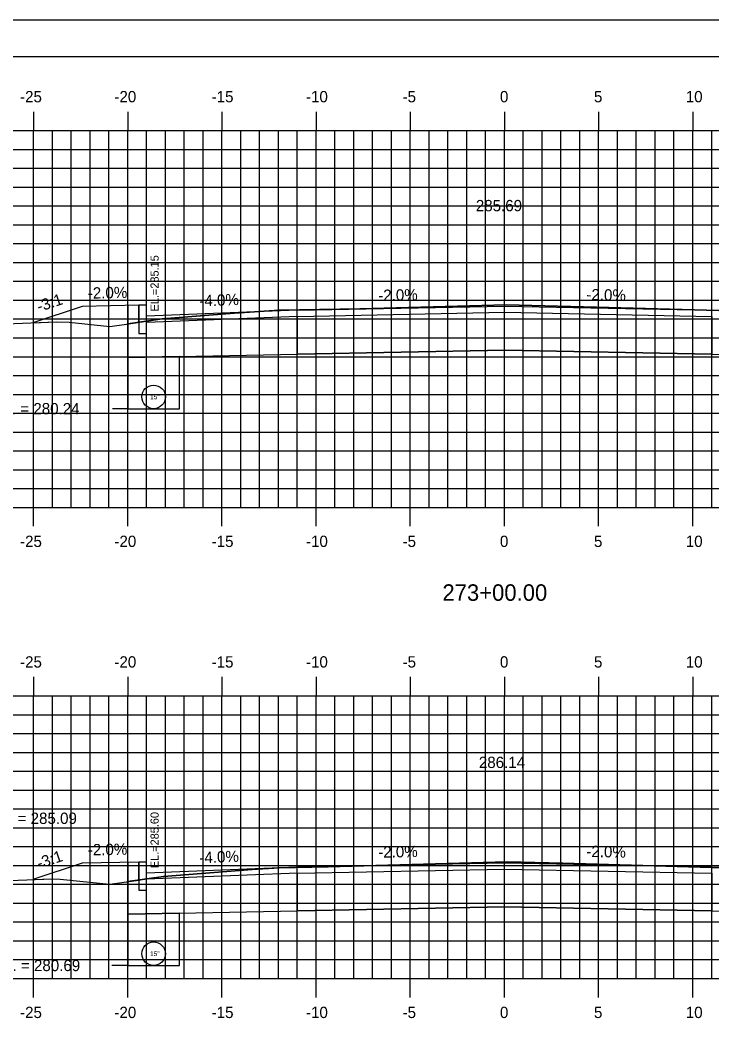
# Model space of a CAD drawing. Extents: x 852672 to 852842, y 366268 to 366378.
# Drawn here: x 852729.4 to 852766.1, y 366324.2 to 366378.2 of the extents above; entities that cross this region are included whole.
import ezdxf

# ---------------------------------------------------------------- set-up
doc = ezdxf.new("R2010")
doc.units = 0
for name, color, linetype in [('ANNOTATION', 7, 'Continuous'), ('BORDER', 7, 'Continuous'), ('D_Curb_Type_1_Lt', 7, 'Continuous'), ('D_Roadway_Centerline_Text', 7, 'Continuous'), ('D_Roadway_Edge_Shoulder', 7, 'Continuous'), ('D_Roadway_FinishedGrade', 7, 'Continuous'), ('D_Roadway_SubGrade', 7, 'Continuous'), ('D_Text_Standard', 7, 'Continuous'), ('H_V ANNOTATION', 7, 'Continuous'), ('JUNK COM EXC', 7, 'Continuous'), ('JUNK FILL', 7, 'Continuous'), ('junk strct exc', 7, 'Continuous'), ('MAJOR', 7, 'Continuous'), ('MINOR', 7, 'Continuous'), ('PDRAIN', 7, 'Continuous'), ('PLOT BOUNDARY', 7, 'Continuous'), ('S_Roadway_Centerline', 7, 'Continuous')]:
    doc.layers.add(name, color=color, linetype=linetype)

msp = doc.modelspace()

# ---------------------------------------------------------------- linework, layer by layer
at = {"layer": 'BORDER'}
msp.add_line((852840.097, 366376.236), (852680.097, 366376.236), dxfattribs=at)
at = {"layer": 'D_Curb_Type_1_Lt'}
for points in [[(852735.68, 366363.057), (852735.68, 366361.557), (852736.096, 366361.557), (852736.096, 366363.057)], [(852735.68, 366333.508), (852735.68, 366332.008), (852736.096, 366332.008), (852736.096, 366333.508)]]:
    msp.add_lwpolyline(points, close=True, dxfattribs=at)
at = {"layer": 'D_Roadway_Edge_Shoulder'}
msp.add_line((852744.096, 366362.793), (852736.096, 366362.473), dxfattribs=at)
for points in [[(852744.096, 366362.793), (852755.096, 366363.013), (852766.096, 366362.793)], [(852736.096, 366332.925), (852744.096, 366333.245), (852755.096, 366333.464), (852766.096, 366333.245), (852774.096, 366332.924)]]:
    msp.add_lwpolyline(points, dxfattribs=at)
at = {"layer": 'D_Roadway_FinishedGrade'}
for points in [[(852732.68, 366362.997), (852730.062, 366362.124)], [(852735.68, 366363.057), (852732.68, 366362.997)], [(852732.68, 366333.448), (852730.063, 366332.576)], [(852735.68, 366333.508), (852732.68, 366333.448)]]:
    msp.add_lwpolyline(points, dxfattribs=at)
at = {"layer": 'D_Roadway_SubGrade'}
for points in [[(852735.096, 366363.045), (852735.096, 366360.28)], [(852735.096, 366360.28), (852744.11, 366360.461), (852744.11, 366362.461), (852736.11, 366362.141)], [(852735.096, 366333.496), (852735.096, 366330.732)], [(852735.096, 366330.732), (852744.106, 366330.912), (852744.106, 366332.912), (852736.096, 366332.591)]]:
    msp.add_lwpolyline(points, dxfattribs=at)
for points in [[(852744.11, 366360.461), (852744.11, 366362.461), (852755.11, 366362.681), (852766.11, 366362.461), (852766.11, 366360.461), (852755.11, 366360.681)], [(852744.106, 366330.912), (852744.106, 366332.912), (852755.106, 366333.132), (852766.106, 366332.912), (852766.106, 366330.912), (852755.106, 366331.132)]]:
    msp.add_lwpolyline(points, close=True, dxfattribs=at)
at = {"layer": 'D_Text_Standard'}
for points in [[(852735.096, 366357.567), (852734.968, 366357.567), (852734.288, 366357.567)], [(852735.096, 366328.017), (852734.936, 366328.017), (852734.256, 366328.017)]]:
    msp.add_lwpolyline(points, dxfattribs=at)
at = {"layer": 'JUNK COM EXC'}
for points in [[(852735.096, 366362.066), (852735.096, 366360.28), (852744.11, 366360.461), (852755.11, 366360.681), (852766.11, 366360.461), (852775.086, 366360.282), (852775.096, 366362.456), (852768.422, 366362.719), (852759.991, 366362.96), (852755.187, 366363.083), (852747.417, 366362.872), (852743.133, 366362.791), (852740.774, 366362.627), (852736.929, 366362.331)], [(852735.096, 366332.469), (852735.096, 366330.732), (852744.106, 366330.912), (852755.106, 366331.132), (852766.106, 366330.912), (852775.096, 366330.732), (852775.096, 366332.352), (852779.101, 366332.433), (852779.101, 366332.787), (852775.096, 366332.902), (852773.379, 366332.951), (852768.512, 366333.143), (852758.198, 366333.438), (852755.238, 366333.514), (852745.742, 366333.256), (852743.139, 366333.207), (852741.706, 366333.107), (852736.999, 366332.744)]]:
    msp.add_lwpolyline(points, close=True, dxfattribs=at)
at = {"layer": 'JUNK FILL'}
for points in [[(852735.68, 366362.15), (852735.68, 366363.057), (852732.68, 366362.997), (852730.062, 366362.124), (852731.301, 366362.174), (852731.997, 366362.154), (852734.142, 366361.931), (852735.024, 366362.055)], [(852735.68, 366332.553), (852735.68, 366333.508), (852732.68, 366333.448), (852730.063, 366332.576), (852731.078, 366332.617), (852731.506, 366332.605), (852734.129, 366332.331), (852734.667, 366332.407)]]:
    msp.add_lwpolyline(points, close=True, dxfattribs=at)
at = {"layer": 'junk strct exc'}
for points in [[(852735.096, 366360.286), (852735.096, 366357.567), (852737.846, 366357.567), (852737.846, 366360.341)], [(852735.096, 366330.736), (852735.096, 366328.017), (852737.846, 366328.017), (852737.846, 366330.791)]]:
    msp.add_lwpolyline(points, close=True, dxfattribs=at)
at = {"layer": 'MAJOR'}
for p, q in [((852730.096, 366373.329), (852730.096, 366372.327)), ((852735.096, 366373.329), (852735.096, 366372.327)), ((852740.096, 366373.329), (852740.096, 366372.327)), ((852745.096, 366373.329), (852745.096, 366372.327)), ((852750.096, 366373.329), (852750.096, 366372.327)), ((852755.096, 366373.329), (852755.096, 366372.327)), ((852760.096, 366373.329), (852760.096, 366372.327)), ((852765.096, 366373.329), (852765.096, 366372.327)), ((852685.096, 366372.327), (852825.096, 366372.327)), ((852685.096, 366372.327), (852825.096, 366372.327)), ((852730.096, 366352.327), (852730.096, 366372.327)), ((852735.096, 366352.327), (852735.096, 366372.327)), ((852740.096, 366352.327), (852740.096, 366372.327)), ((852745.096, 366352.327), (852745.096, 366372.327)), ((852750.096, 366352.327), (852750.096, 366372.327)), ((852755.096, 366352.327), (852755.096, 366372.327)), ((852760.096, 366352.327), (852760.096, 366372.327)), ((852765.096, 366352.327), (852765.096, 366372.327)), ((852685.096, 366367.327), (852825.096, 366367.327)), ((852685.096, 366362.327), (852825.096, 366362.327)), ((852685.096, 366357.327), (852825.096, 366357.327)), ((852685.096, 366352.327), (852825.096, 366352.327)), ((852685.096, 366352.327), (852825.096, 366352.327)), ((852730.096, 366351.325), (852730.096, 366352.327)), ((852735.096, 366351.325), (852735.096, 366352.327)), ((852740.096, 366351.325), (852740.096, 366352.327)), ((852745.096, 366351.325), (852745.096, 366352.327)), ((852750.096, 366351.325), (852750.096, 366352.327)), ((852755.096, 366351.325), (852755.096, 366352.327)), ((852760.096, 366351.325), (852760.096, 366352.327)), ((852765.096, 366351.325), (852765.096, 366352.327)), ((852730.096, 366343.329), (852730.096, 366342.327)), ((852735.096, 366343.329), (852735.096, 366342.327)), ((852740.096, 366343.329), (852740.096, 366342.327)), ((852745.096, 366343.329), (852745.096, 366342.327)), ((852750.096, 366343.329), (852750.096, 366342.327)), ((852755.096, 366343.329), (852755.096, 366342.327)), ((852760.096, 366343.329), (852760.096, 366342.327)), ((852765.096, 366343.329), (852765.096, 366342.327)), ((852685.096, 366342.327), (852825.096, 366342.327)), ((852685.096, 366342.327), (852825.096, 366342.327)), ((852730.096, 366327.327), (852730.096, 366342.327)), ((852735.096, 366327.327), (852735.096, 366342.327)), ((852740.096, 366327.327), (852740.096, 366342.327)), ((852745.096, 366327.327), (852745.096, 366342.327)), ((852750.096, 366327.327), (852750.096, 366342.327)), ((852755.096, 366327.327), (852755.096, 366342.327)), ((852760.096, 366327.327), (852760.096, 366342.327)), ((852765.096, 366327.327), (852765.096, 366342.327)), ((852685.096, 366337.327), (852825.096, 366337.327)), ((852685.096, 366332.327), (852825.096, 366332.327)), ((852685.096, 366327.327), (852825.096, 366327.327)), ((852685.096, 366327.327), (852825.096, 366327.327)), ((852730.096, 366326.325), (852730.096, 366327.327)), ((852735.096, 366326.325), (852735.096, 366327.327)), ((852740.096, 366326.325), (852740.096, 366327.327)), ((852745.096, 366326.325), (852745.096, 366327.327)), ((852750.096, 366326.325), (852750.096, 366327.327)), ((852755.096, 366326.325), (852755.096, 366327.327)), ((852760.096, 366326.325), (852760.096, 366327.327)), ((852765.096, 366326.325), (852765.096, 366327.327))]:
    msp.add_line(p, q, dxfattribs=at)
at = {"layer": 'MINOR'}
for p, q in [((852731.096, 366352.327), (852731.096, 366372.327)), ((852732.096, 366352.327), (852732.096, 366372.327)), ((852733.096, 366352.327), (852733.096, 366372.327)), ((852734.096, 366352.327), (852734.096, 366372.327)), ((852736.096, 366352.327), (852736.096, 366372.327)), ((852737.096, 366352.327), (852737.096, 366372.327)), ((852738.096, 366352.327), (852738.096, 366372.327)), ((852739.096, 366352.327), (852739.096, 366372.327)), ((852741.096, 366352.327), (852741.096, 366372.327)), ((852742.096, 366352.327), (852742.096, 366372.327)), ((852743.096, 366352.327), (852743.096, 366372.327)), ((852744.096, 366352.327), (852744.096, 366372.327)), ((852746.096, 366352.327), (852746.096, 366372.327)), ((852747.096, 366352.327), (852747.096, 366372.327)), ((852748.096, 366352.327), (852748.096, 366372.327)), ((852749.096, 366352.327), (852749.096, 366372.327)), ((852751.096, 366352.327), (852751.096, 366372.327)), ((852752.096, 366352.327), (852752.096, 366372.327)), ((852753.096, 366352.327), (852753.096, 366372.327)), ((852754.096, 366352.327), (852754.096, 366372.327)), ((852756.096, 366352.327), (852756.096, 366372.327)), ((852757.096, 366352.327), (852757.096, 366372.327)), ((852758.096, 366352.327), (852758.096, 366372.327)), ((852759.096, 366352.327), (852759.096, 366372.327)), ((852761.096, 366352.327), (852761.096, 366372.327)), ((852762.096, 366352.327), (852762.096, 366372.327)), ((852763.096, 366352.327), (852763.096, 366372.327)), ((852764.096, 366352.327), (852764.096, 366372.327)), ((852766.096, 366352.327), (852766.096, 366372.327)), ((852685.096, 366371.327), (852825.096, 366371.327)), ((852685.096, 366370.327), (852825.096, 366370.327)), ((852685.096, 366369.327), (852825.096, 366369.327)), ((852685.096, 366368.327), (852825.096, 366368.327)), ((852685.096, 366366.327), (852825.096, 366366.327)), ((852685.096, 366365.327), (852825.096, 366365.327)), ((852685.096, 366364.327), (852825.096, 366364.327)), ((852685.096, 366363.327), (852825.096, 366363.327)), ((852685.096, 366361.327), (852825.096, 366361.327)), ((852685.096, 366360.327), (852825.096, 366360.327)), ((852685.096, 366359.327), (852825.096, 366359.327)), ((852685.096, 366358.327), (852825.096, 366358.327)), ((852685.096, 366356.327), (852825.096, 366356.327)), ((852685.096, 366355.327), (852825.096, 366355.327)), ((852685.096, 366354.327), (852825.096, 366354.327)), ((852685.096, 366353.327), (852825.096, 366353.327)), ((852731.096, 366327.327), (852731.096, 366342.327)), ((852732.096, 366327.327), (852732.096, 366342.327)), ((852733.096, 366327.327), (852733.096, 366342.327)), ((852734.096, 366327.327), (852734.096, 366342.327)), ((852736.096, 366327.327), (852736.096, 366342.327)), ((852737.096, 366327.327), (852737.096, 366342.327)), ((852738.096, 366327.327), (852738.096, 366342.327)), ((852739.096, 366327.327), (852739.096, 366342.327)), ((852741.096, 366327.327), (852741.096, 366342.327)), ((852742.096, 366327.327), (852742.096, 366342.327)), ((852743.096, 366327.327), (852743.096, 366342.327)), ((852744.096, 366327.327), (852744.096, 366342.327)), ((852746.096, 366327.327), (852746.096, 366342.327)), ((852747.096, 366327.327), (852747.096, 366342.327)), ((852748.096, 366327.327), (852748.096, 366342.327)), ((852749.096, 366327.327), (852749.096, 366342.327)), ((852751.096, 366327.327), (852751.096, 366342.327)), ((852752.096, 366327.327), (852752.096, 366342.327)), ((852753.096, 366327.327), (852753.096, 366342.327)), ((852754.096, 366327.327), (852754.096, 366342.327)), ((852756.096, 366327.327), (852756.096, 366342.327)), ((852757.096, 366327.327), (852757.096, 366342.327)), ((852758.096, 366327.327), (852758.096, 366342.327)), ((852759.096, 366327.327), (852759.096, 366342.327)), ((852761.096, 366327.327), (852761.096, 366342.327)), ((852762.096, 366327.327), (852762.096, 366342.327)), ((852763.096, 366327.327), (852763.096, 366342.327)), ((852764.096, 366327.327), (852764.096, 366342.327)), ((852766.096, 366327.327), (852766.096, 366342.327)), ((852685.096, 366341.327), (852825.096, 366341.327)), ((852685.096, 366340.327), (852825.096, 366340.327)), ((852685.096, 366339.327), (852825.096, 366339.327)), ((852685.096, 366338.327), (852825.096, 366338.327)), ((852685.096, 366336.327), (852825.096, 366336.327)), ((852685.096, 366335.327), (852825.096, 366335.327)), ((852685.096, 366334.327), (852825.096, 366334.327)), ((852685.096, 366333.327), (852825.096, 366333.327)), ((852685.096, 366331.327), (852825.096, 366331.327)), ((852685.096, 366330.327), (852825.096, 366330.327)), ((852685.096, 366329.327), (852825.096, 366329.327)), ((852685.096, 366328.327), (852825.096, 366328.327))]:
    msp.add_line(p, q, dxfattribs=at)
at = {"layer": 'PDRAIN'}
for points in [[(852735.096, 366360.28), (852735.096, 366357.567), (852737.846, 366357.567), (852737.846, 366360.335)], [(852735.096, 366330.732), (852735.096, 366328.017), (852737.846, 366328.017), (852737.846, 366330.787)]]:
    msp.add_lwpolyline(points, dxfattribs=at)
for centre in [(852736.471, 366358.192), (852736.471, 366328.642)]:
    msp.add_circle(centre, 0.625, dxfattribs=at)
at = {"layer": 'PLOT BOUNDARY'}
msp.add_lwpolyline([(852672.003, 366268.177), (852842.003, 366268.177), (852842.003, 366378.177), (852672.003, 366378.177)], close=True, dxfattribs=at)
at = {"layer": 'S_Roadway_Centerline'}
for points in [[(852706.614, 366362.002), (852711.434, 366361.992), (852721.194, 366361.85), (852723.222, 366361.85), (852731.301, 366362.174), (852731.997, 366362.154), (852734.142, 366361.931), (852735.024, 366362.055), (852736.929, 366362.331), (852740.774, 366362.627), (852743.133, 366362.791), (852747.417, 366362.872), (852755.187, 366363.083), (852759.991, 366362.96), (852768.422, 366362.719), (852776.31, 366362.408), (852781.428, 366362.26), (852782.594, 366362.294), (852784.415, 366362.377), (852787.287, 366362.402), (852792.84, 366362.746), (852804.042, 366363.313), (852809.881, 366363.563), (852812.01, 366363.649)], [(852726.107, 366332.417), (852731.078, 366332.617), (852731.506, 366332.605), (852734.129, 366332.331), (852734.667, 366332.407), (852736.999, 366332.744), (852741.706, 366333.107), (852743.139, 366333.207), (852745.742, 366333.256), (852755.238, 366333.514), (852758.198, 366333.438), (852768.512, 366333.143), (852773.379, 366332.951), (852778.991, 366332.79), (852781.492, 366332.725), (852781.726, 366332.983), (852781.821, 366333.046), (852782.579, 366333.14), (852784.69, 366333.411), (852789.288, 366333.459), (852792.255, 366333.487), (852804.55, 366333.744)]]:
    msp.add_lwpolyline(points, dxfattribs=at)

# ---------------------------------------------------------------- texts
at = {"layer": 'ANNOTATION'}
for s, rotation, p in [('-2.0%', 1.1458, (852732.983, 366363.403)), ('-2.0%', 1.1458, (852748.4, 366363.28)), ('-2.0%', 358.8542, (852759.44, 366363.327)), ('-3:1', 18.4349, (852730.388, 366362.687)), ('-4.0%', 2.2906, (852738.912, 366362.987)), ('-2.0%', 1.1458, (852732.983, 366333.854)), ('-2.0%', 1.1458, (852748.4, 366333.731)), ('-2.0%', 358.8542, (852759.44, 366333.778)), ('-3:1', 18.4349, (852730.389, 366333.138)), ('-4.0%', 2.2906, (852738.912, 366333.438))]:
    msp.add_text(s, height=0.6, rotation=rotation, dxfattribs=at).set_placement(p)
at = {"layer": 'D_Roadway_Centerline_Text'}
for s, p in [('285.69', (852753.577, 366368.045)), ('286.14', (852753.737, 366338.496))]:
    msp.add_text(s, height=0.6, dxfattribs=at).set_placement(p)
at = {"layer": 'D_Text_Standard'}
for s, p in [(' EL.=285.15', (852736.74, 366362.567)), (' EL.=285.60', (852736.74, 366333.019))]:
    msp.add_text(s, height=0.4335, rotation=90, dxfattribs=at).set_placement(p)
for s, p in [('ELEV. = 280.24', (852726.899, 366357.267)), ('ELEV. = 285.09', (852726.755, 366335.529)), ('ELEV. = 280.69', (852726.931, 366327.717))]:
    msp.add_text(s, height=0.6, dxfattribs=at).set_placement(p)
at = {"layer": 'H_V ANNOTATION'}
for s, height, p in [('-25', 0.6, (852729.382, 366373.827)), ('-20', 0.6, (852734.39, 366373.827)), ('-15', 0.6, (852739.553, 366373.827)), ('-10', 0.6, (852744.561, 366373.827)), ('-5', 0.6, (852749.687, 366373.827)), ('0', 0.6, (852754.856, 366373.827)), ('5', 0.6, (852759.848, 366373.827)), ('10', 0.6, (852764.722, 366373.827)), ('-25', 0.6, (852729.382, 366350.227)), ('-20', 0.6, (852734.39, 366350.227)), ('-15', 0.6, (852739.553, 366350.227)), ('-10', 0.6, (852744.561, 366350.227)), ('-5', 0.6, (852749.687, 366350.227)), ('0', 0.6, (852754.856, 366350.227)), ('5', 0.6, (852759.848, 366350.227)), ('10', 0.6, (852764.722, 366350.227)), ('273+00.00', 0.875, (852751.803, 366347.37)), ('-25', 0.6, (852729.382, 366343.827)), ('-20', 0.6, (852734.39, 366343.827)), ('-15', 0.6, (852739.553, 366343.827)), ('-10', 0.6, (852744.561, 366343.827)), ('-5', 0.6, (852749.687, 366343.827)), ('0', 0.6, (852754.856, 366343.827)), ('5', 0.6, (852759.848, 366343.827)), ('10', 0.6, (852764.722, 366343.827)), ('-25', 0.6, (852729.382, 366325.227)), ('-20', 0.6, (852734.39, 366325.227)), ('-15', 0.6, (852739.553, 366325.227)), ('-10', 0.6, (852744.561, 366325.227)), ('-5', 0.6, (852749.687, 366325.227)), ('0', 0.6, (852754.856, 366325.227)), ('5', 0.6, (852759.848, 366325.227)), ('10', 0.6, (852764.722, 366325.227))]:
    msp.add_text(s, height=height, dxfattribs=at).set_placement(p)
at = {"layer": 'PDRAIN'}
for p in [(852736.284, 366358.067), (852736.284, 366328.517)]:
    msp.add_text('15"', height=0.25, dxfattribs=at).set_placement(p)
at = {"layer": 'S_Roadway_Centerline'}
for s, p in [('C', (852755.182, 366363.083)), ('L', (852755.187, 366363.076)), ('C', (852755.232, 366333.514)), ('L', (852755.238, 366333.507))]:
    msp.add_text(s, height=0.0146, dxfattribs=at).set_placement(p)

doc.saveas('drawing.dxf')
